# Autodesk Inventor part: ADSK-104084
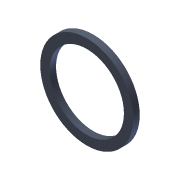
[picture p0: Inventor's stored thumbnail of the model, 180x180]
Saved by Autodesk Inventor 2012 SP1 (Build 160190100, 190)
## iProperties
Shininess: 27.0
Created: 2001-04
Part Number: ADSK-104084
Document SubType Name: Modeling
Designer: Administrator
Stock Number: ADSK-104084
Density: 1 g/cm^3
Material: Default
Density: 0.0
Volumn: 0.0
Area: 0.0
PropertySet Name: Model Information
Control State: 0
Master: False
Checked Out: False
Author: Administrator
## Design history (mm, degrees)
sketch "Sketch1"
  geometry: C1 r 31.75 at (0, 0); C2 r 25.4 at (0, 0)
  constraints: 2 centre point
  dimensions: "d0" = 50.8 diameter of C2; "d1" = 63.5 diameter of C1
extrude "Extrusion1" new body sketch "Sketch1" distance "d2" = 4.445; taper "d3" = 0 deg
body "Solid1"
